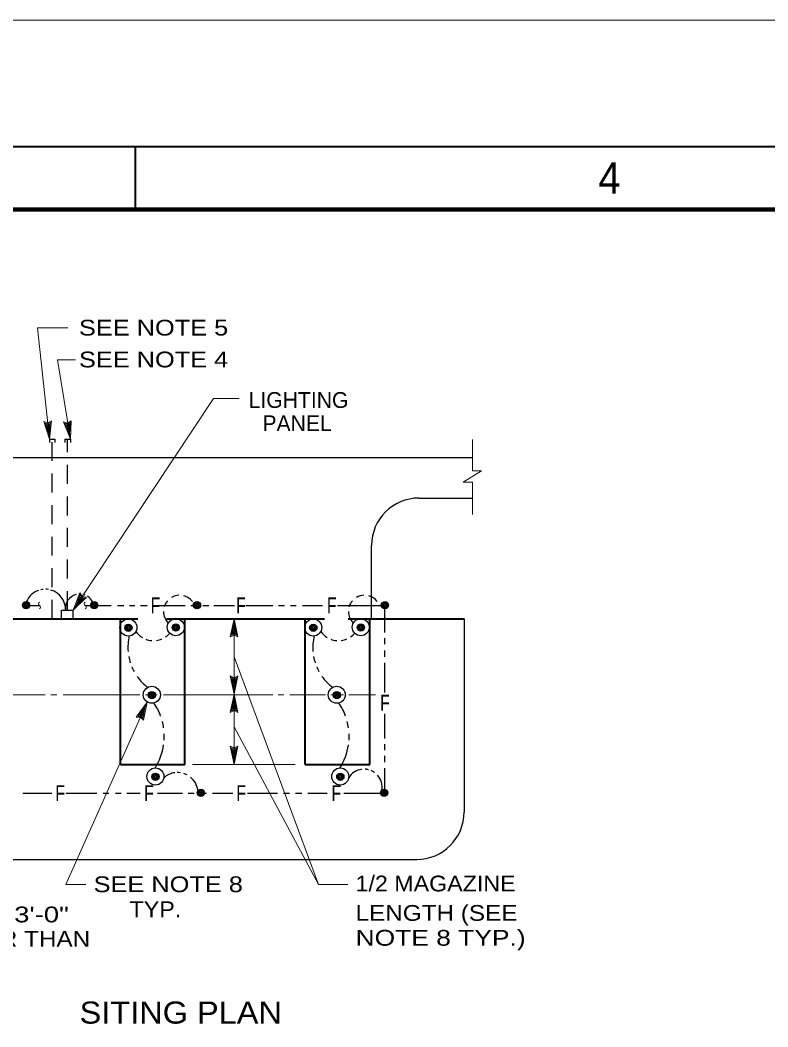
# Model space of a CAD drawing. Extents: x -39.6 to 16.1, y -17.6 to 34.
# Drawn here: x -17.81 to -11.89, y 4.44 to 12.41 of the extents above; entities that cross this region are included whole.
import ezdxf
from ezdxf.enums import TextEntityAlignment as Align

# ---------------------------------------------------------------- set-up
doc = ezdxf.new("R2010")
doc.units = 0
doc.header["$LTSCALE"] = 0.05
doc.linetypes.add('MEDIUM_DASHED', pattern=[4.5, 3, -1.5])
doc.layers.add('1', color=7, linetype='Continuous', lineweight=13)

msp = doc.modelspace()

# ---------------------------------------------------------------- linework, layer by layer
at = {"layer": '1', "lineweight": 40}
for p, q in [((-16.89821, 11.40842), (-16.89821, 10.90842)), ((-18.13621, 7.66742), (-16.87721, 7.66742)), ((-17.01421, 6.51442), (-17.01421, 7.66742)), ((-16.64921, 7.66742), (-15.39721, 7.66742)), ((-16.50321, 6.51442), (-16.50321, 7.66742)), ((-15.55021, 6.51442), (-15.55021, 7.66742)), ((-15.21021, 7.66742), (-14.29321, 7.66742)), ((-15.03921, 6.51442), (-15.03921, 7.66742)), ((-17.01421, 6.51442), (-16.50321, 6.51442)), ((-15.55021, 6.51442), (-15.03921, 6.51442))]:
    msp.add_line(p, q, dxfattribs=at)
at = {"layer": '1'}
for p, q in [((-17.67021, 9.97142), (-17.43121, 9.97142)), ((-17.67021, 9.97142), (-17.57521, 9.08942)), ((-17.51321, 9.71942), (-17.36921, 9.71942)), ((-17.51321, 9.71942), (-17.41021, 9.08942)), ((-16.27821, 9.41242), (-16.07321, 9.41242)), ((-17.57521, 9.08942), (-17.62121, 9.22942)), ((-17.57921, 9.12642), (-17.60921, 9.21742)), ((-17.60921, 9.21742), (-17.58821, 9.21042)), ((-17.58321, 9.16242), (-17.59821, 9.20542)), ((-17.59821, 9.20542), (-17.58721, 9.20242)), ((-17.58821, 9.21042), (-17.56921, 9.22142)), ((-17.58721, 9.20242), (-17.57921, 9.20742)), ((-17.58321, 9.16242), (-17.57921, 9.20742)), ((-17.57921, 9.12642), (-17.56921, 9.22142)), ((-17.57521, 9.08942), (-17.56021, 9.23542)), ((-17.41021, 9.08942), (-17.46421, 9.22642)), ((-17.41621, 9.12642), (-17.45121, 9.21542)), ((-17.45121, 9.21542), (-17.43021, 9.20942)), ((-17.42221, 9.16142), (-17.43921, 9.20442)), ((-17.43921, 9.20442), (-17.42821, 9.20242)), ((-17.43021, 9.20942), (-17.41121, 9.22242)), ((-17.42821, 9.20242), (-17.42021, 9.20742)), ((-17.42221, 9.16142), (-17.42021, 9.20742)), ((-17.41621, 9.12642), (-17.41121, 9.22242)), ((-17.41021, 9.08942), (-17.40321, 9.23642)), ((-14.22521, 8.83842), (-14.22521, 9.08642)), ((-14.29921, 8.74842), (-14.15421, 8.83842)), ((-14.22521, 8.83842), (-14.15421, 8.83842)), ((-14.29921, 8.74842), (-14.22521, 8.74842)), ((-14.22521, 8.49342), (-14.22521, 8.74842)), ((-17.38821, 7.73642), (-17.28321, 7.83942)), ((-17.36821, 7.76742), (-17.33221, 7.85642)), ((-17.36821, 7.76742), (-17.29921, 7.83442)), ((-17.34821, 7.79742), (-17.33121, 7.84042)), ((-17.34821, 7.79742), (-17.31521, 7.82942)), ((-17.33221, 7.85642), (-17.32121, 7.83842)), ((-17.33121, 7.84042), (-17.32521, 7.83142)), ((-17.32521, 7.83142), (-17.31521, 7.82942)), ((-17.32121, 7.83842), (-17.29921, 7.83442)), ((-16.11421, 7.66742), (-16.14521, 7.52342)), ((-16.11421, 7.66742), (-16.08321, 7.52342)), ((-16.11421, 7.63042), (-16.13421, 7.53642)), ((-16.11421, 7.59442), (-16.12321, 7.54942)), ((-16.11421, 7.63042), (-16.09421, 7.53642)), ((-16.11421, 7.59442), (-16.10421, 7.54942)), ((-16.11421, 7.54542), (-16.13421, 7.53642)), ((-16.11421, 7.55342), (-16.12321, 7.54942)), ((-16.10421, 7.54942), (-16.11421, 7.55342)), ((-16.09421, 7.53642), (-16.11421, 7.54542)), ((-16.11421, 7.36542), (-15.44621, 5.56442)), ((-16.11421, 7.07042), (-16.14521, 7.21442)), ((-16.11421, 7.10742), (-16.13421, 7.20142)), ((-16.13421, 7.20142), (-16.11421, 7.19242)), ((-16.11421, 7.14342), (-16.12421, 7.18842)), ((-16.12421, 7.18842), (-16.11421, 7.18442)), ((-16.11421, 7.07042), (-16.08321, 7.21442)), ((-16.11421, 7.10742), (-16.09421, 7.20142)), ((-16.11421, 7.19242), (-16.09421, 7.20142)), ((-16.11421, 7.14342), (-16.10521, 7.18842)), ((-16.11421, 7.18442), (-16.10521, 7.18842)), ((-18.16521, 7.06442), (-17.61021, 7.06442)), ((-17.56621, 7.06442), (-17.51821, 7.06442)), ((-17.46721, 7.06442), (-16.86021, 7.06442)), ((-16.81421, 7.06442), (-16.72321, 7.06442)), ((-16.67421, 7.06442), (-15.80721, 7.06442)), ((-16.11421, 7.07042), (-16.14521, 6.92642)), ((-16.11421, 7.03342), (-16.13421, 6.93942)), ((-16.11421, 7.07042), (-16.08321, 6.92642)), ((-16.11421, 7.03342), (-16.09421, 6.93942)), ((-15.76621, 7.06442), (-15.71921, 7.06442)), ((-15.67321, 7.06442), (-15.38921, 7.06442)), ((-15.34721, 7.06442), (-15.24821, 7.06442)), ((-15.20521, 7.06442), (-14.99521, 7.06442)), ((-16.80221, 7.00842), (-16.88921, 6.88942)), ((-16.81721, 6.97442), (-16.87421, 6.89642)), ((-16.83221, 6.94142), (-16.85821, 6.90442)), ((-16.83221, 6.94142), (-16.84121, 6.89642)), ((-16.81721, 6.97442), (-16.83721, 6.88042)), ((-16.80221, 7.00842), (-16.83221, 6.86442)), ((-16.11421, 6.94842), (-16.13421, 6.93942)), ((-16.11421, 6.99742), (-16.12321, 6.95242)), ((-16.11421, 6.95642), (-16.12321, 6.95242)), ((-16.11421, 6.99742), (-16.10421, 6.95242)), ((-16.10421, 6.95242), (-16.11421, 6.95642)), ((-16.09421, 6.93942), (-16.11421, 6.94842)), ((-16.85221, 6.89742), (-16.87421, 6.89642)), ((-16.84821, 6.90442), (-16.85821, 6.90442)), ((-16.83721, 6.88042), (-16.85221, 6.89742)), ((-16.84121, 6.89642), (-16.84821, 6.90442)), ((-16.11421, 6.51442), (-16.14521, 6.65842)), ((-16.11421, 6.55142), (-16.13421, 6.64542)), ((-16.13421, 6.64542), (-16.11421, 6.63642)), ((-16.11421, 6.58742), (-16.12421, 6.63242)), ((-16.12421, 6.63242), (-16.11421, 6.62842)), ((-16.11421, 6.51442), (-16.08321, 6.65842)), ((-16.11421, 6.55142), (-16.09421, 6.64542)), ((-16.11421, 6.63642), (-16.09421, 6.64542)), ((-16.11421, 6.58742), (-16.10521, 6.63242)), ((-16.11421, 6.62842), (-16.10521, 6.63242)), ((-16.44221, 6.51442), (-15.63021, 6.51442))]:
    msp.add_line(p, q, dxfattribs=at)
at = {"layer": '1', "lineweight": 25}
for p, q in [((-17.57521, 9.08942), (-17.53321, 9.08942)), ((-17.57521, 9.08942), (-17.57521, 9.06342)), ((-17.53321, 9.08942), (-17.53321, 9.06342)), ((-17.45421, 9.08942), (-17.45421, 9.06342)), ((-20.55621, 8.94342), (-14.22521, 8.94342)), ((-14.65021, 8.62342), (-14.22521, 8.62342)), ((-15.02521, 7.66742), (-15.02521, 8.24842)), ((-17.77721, 7.77342), (-17.65521, 7.77342)), ((-17.47921, 7.66742), (-17.47921, 7.73642)), ((-17.47921, 7.73642), (-17.38821, 7.73642)), ((-17.38821, 7.66742), (-17.38821, 7.73642)), ((-17.29221, 7.77342), (-17.08821, 7.77342)), ((-17.03821, 7.77342), (-16.98721, 7.77342)), ((-16.94221, 7.77342), (-16.90021, 7.77342)), ((-16.85521, 7.77342), (-16.80221, 7.77342)), ((-16.71221, 7.77342), (-16.50121, 7.77342)), ((-16.45621, 7.77342), (-16.40921, 7.77342)), ((-16.36021, 7.77342), (-16.31521, 7.77342)), ((-16.27321, 7.77342), (-16.11121, 7.77342)), ((-16.02121, 7.77342), (-15.80821, 7.77342)), ((-15.76321, 7.77342), (-15.71421, 7.77342)), ((-15.66821, 7.77342), (-15.62121, 7.77342)), ((-15.57321, 7.77342), (-15.41321, 7.77342)), ((-15.29521, 7.77342), (-14.92221, 7.77342)), ((-14.92221, 7.77342), (-14.92221, 7.55942)), ((-14.29321, 7.66742), (-14.29321, 6.13642)), ((-14.92221, 7.51442), (-14.92221, 7.46742)), ((-14.92221, 7.41642), (-14.92221, 7.36542)), ((-14.92221, 7.31742), (-14.92221, 7.08242)), ((-14.92221, 6.91442), (-14.92221, 6.71842)), ((-14.92221, 6.67342), (-14.92221, 6.62642)), ((-14.92221, 6.58142), (-14.92221, 6.53242)), ((-14.92221, 6.48542), (-14.92221, 6.28642)), ((-17.78621, 6.28642), (-17.55621, 6.28642)), ((-17.44521, 6.28642), (-17.20121, 6.28642)), ((-17.15021, 6.28642), (-17.10521, 6.28642)), ((-17.05421, 6.28642), (-17.00921, 6.28642)), ((-16.96221, 6.28642), (-16.85821, 6.28642)), ((-16.71921, 6.28642), (-16.52321, 6.28642)), ((-16.47821, 6.28642), (-16.43121, 6.28642)), ((-16.38021, 6.28642), (-16.33121, 6.28642)), ((-16.28621, 6.28642), (-16.12521, 6.28642)), ((-16.00721, 6.28642), (-15.77021, 6.28642)), ((-15.72321, 6.28642), (-15.67421, 6.28642)), ((-15.62721, 6.28642), (-15.57821, 6.28642)), ((-15.53121, 6.28642), (-15.37821, 6.28642)), ((-15.24621, 6.28642), (-14.92221, 6.28642)), ((-20.29221, 5.76142), (-14.66821, 5.76142))]:
    msp.add_line(p, q, dxfattribs=at)
at = {"layer": '1', "linetype": 'MEDIUM_DASHED', "lineweight": 25}
for p, q in [((-17.55521, 7.66742), (-17.55521, 9.08942)), ((-17.43421, 7.73642), (-17.43421, 9.08942))]:
    msp.add_line(p, q, dxfattribs=at)
at = {"layer": '1'}
for points in [[(-25.89821, 12.40842), (16.10179, 12.40842), (16.10179, -17.59158)], [(-16.27821, 9.41242), (-17.38821, 7.73642), (-17.33421, 7.87342)], [(-17.62121, 9.22942), (-17.58921, 9.21842), (-17.56021, 9.23542)], [(-17.46421, 9.22642), (-17.43121, 9.21742), (-17.40321, 9.23642)], [(-17.33421, 7.87342), (-17.31621, 7.84442), (-17.28321, 7.83942)], [(-16.11421, 6.51442), (-16.11421, 7.07042), (-16.11421, 7.66742)], [(-16.08321, 7.52342), (-16.11421, 7.53742), (-16.14521, 7.52342)], [(-16.14521, 7.21442), (-16.11421, 7.20042), (-16.08321, 7.21442)], [(-16.80221, 7.00842), (-17.44521, 5.56442), (-17.28721, 5.56442)], [(-16.08321, 6.92642), (-16.11421, 6.94042), (-16.14521, 6.92642)], [(-16.83221, 6.86442), (-16.85521, 6.88942), (-16.88921, 6.88942)], [(-16.11421, 6.81242), (-15.44621, 5.56442), (-15.21421, 5.56442)], [(-16.14521, 6.65842), (-16.11421, 6.64442), (-16.08321, 6.65842)]]:
    msp.add_lwpolyline(points, dxfattribs=at)
at = {"layer": '1', "lineweight": 40}
msp.add_lwpolyline([(-24.89821, -16.59158), (-24.89821, 11.40842), (15.10179, 11.40842), (15.10179, -16.59158)], close=True, dxfattribs=at)
at = {"layer": '1', "lineweight": 90}
msp.add_lwpolyline([(-23.39821, 10.90842), (14.60179, 10.90842), (14.60179, -16.09158), (-23.39821, -16.09158)], close=True, dxfattribs=at)
at = {"layer": '1', "lineweight": 25}
msp.add_lwpolyline([(-17.45421, 9.08942), (-17.41021, 9.08942), (-17.41021, 9.06342)], dxfattribs=at)
for centre, radius in [((-17.76083, 7.77548), 0.02891), ((-17.76083, 7.77548), 0.02242), ((-17.76083, 7.77548), 0.01644), ((-17.76083, 7.77548), 0.0083), ((-17.22183, 7.77548), 0.02891), ((-17.22183, 7.77548), 0.02242), ((-17.22183, 7.77548), 0.01644), ((-17.22183, 7.77548), 0.0083), ((-16.40783, 7.77548), 0.02891), ((-16.40783, 7.77548), 0.02242), ((-16.40783, 7.77548), 0.01644), ((-16.40783, 7.77548), 0.0083), ((-14.91983, 7.77548), 0.02891), ((-14.91983, 7.77548), 0.02242), ((-14.91983, 7.77548), 0.01644), ((-14.91983, 7.77548), 0.0083), ((-16.95121, 7.59842), 0.06748), ((-16.57521, 7.60042), 0.06748), ((-15.48721, 7.59842), 0.06748), ((-15.11121, 7.60042), 0.06748), ((-16.95083, 7.59648), 0.02891), ((-16.95083, 7.59648), 0.02242), ((-16.95083, 7.59648), 0.01644), ((-16.95083, 7.59648), 0.0083), ((-16.57483, 7.59848), 0.02891), ((-16.57483, 7.59848), 0.02242), ((-16.57483, 7.59848), 0.01644), ((-16.57483, 7.59848), 0.0083), ((-15.48683, 7.59648), 0.02891), ((-15.48683, 7.59648), 0.02242), ((-15.48683, 7.59648), 0.01644), ((-15.48683, 7.59648), 0.0083), ((-15.11083, 7.59848), 0.02891), ((-15.11083, 7.59848), 0.02242), ((-15.11083, 7.59848), 0.01644), ((-15.11083, 7.59848), 0.0083), ((-16.76521, 7.06542), 0.06748), ((-15.30121, 7.06542), 0.06748), ((-16.76483, 7.06348), 0.02891), ((-16.76483, 7.06348), 0.02242), ((-16.76483, 7.06348), 0.01644), ((-16.76483, 7.06348), 0.0083), ((-15.30083, 7.06348), 0.02891), ((-15.30083, 7.06348), 0.02242), ((-15.30083, 7.06348), 0.01644), ((-15.30083, 7.06348), 0.0083), ((-16.73721, 6.41842), 0.06748), ((-15.27321, 6.41842), 0.06748), ((-16.73683, 6.41648), 0.02891), ((-16.73683, 6.41648), 0.02242), ((-16.73683, 6.41648), 0.01644), ((-16.73683, 6.41648), 0.0083), ((-15.27283, 6.41648), 0.02891), ((-15.27283, 6.41648), 0.02242), ((-15.27283, 6.41648), 0.01644), ((-15.27283, 6.41648), 0.0083), ((-16.37783, 6.28848), 0.02891), ((-16.37783, 6.28848), 0.02242), ((-16.37783, 6.28848), 0.01644), ((-14.92683, 6.28848), 0.02891), ((-14.92683, 6.28848), 0.02242), ((-14.92683, 6.28848), 0.01644), ((-16.37783, 6.28848), 0.0083), ((-14.92683, 6.28848), 0.0083)]:
    msp.add_circle(centre, radius, dxfattribs=at)
for centre, radius, start, end in [((-14.65021, 8.24842), 0.375, 90, 180), ((-17.6097, 7.7399), 0.16153, 95.51978, 102.08511), ((-17.6097, 7.7399), 0.16153, 80.92201, 88.39851), ((-17.6097, 7.7399), 0.16153, 358.76497, 73.45795), ((-17.6097, 7.7399), 0.16153, 109.11489, 156.84363), ((-17.33587, 7.74959), 0.1141, 105.05257, 186.63192), ((-17.33587, 7.74959), 0.1141, 84.15174, 94.19147), ((-17.33587, 7.74959), 0.1141, 67.58065, 75.01745), ((-17.33587, 7.74959), 0.1141, 27.0109, 57.77622), ((-16.54521, 7.72558), 0.12812, 92.31217, 119.67381), ((-16.54521, 7.72558), 0.12812, 37.97304, 74.64705), ((-15.08121, 7.72558), 0.12812, 92.31217, 119.67381), ((-15.08121, 7.72558), 0.12812, 37.97304, 74.64705), ((-16.54521, 7.72558), 0.12812, 138.45731, 163.45632), ((-15.08121, 7.72558), 0.12812, 138.45731, 163.45632), ((-16.54521, 7.72558), 0.12812, 180.07346, 226.00139), ((-15.08121, 7.72558), 0.12812, 180.07346, 226.00139), ((-16.56002, 7.43955), 0.39502, 166.55144, 184.64806), ((-16.75212, 7.66682), 0.17235, 215.62869, 239.35965), ((-16.75212, 7.66682), 0.17235, 249.22563, 265.63288), ((-16.75212, 7.66682), 0.17235, 277.50113, 292.89982), ((-16.75212, 7.66682), 0.17235, 303.86286, 318.41281), ((-15.09602, 7.43955), 0.39502, 166.55144, 184.64806), ((-15.28812, 7.66682), 0.17235, 215.62869, 239.35965), ((-15.28812, 7.66682), 0.17235, 249.22563, 265.63288), ((-15.28812, 7.66682), 0.17235, 277.50113, 292.89982), ((-15.28812, 7.66682), 0.17235, 303.86286, 318.41281), ((-16.56002, 7.43955), 0.39502, 190.46253, 197.79365), ((-15.09602, 7.43955), 0.39502, 190.46253, 197.79365), ((-16.56002, 7.43955), 0.39502, 202.86164, 208.84607), ((-15.09602, 7.43955), 0.39502, 202.86164, 208.84607), ((-16.56002, 7.43955), 0.39502, 215.36971, 232.91665), ((-15.09602, 7.43955), 0.39502, 215.36971, 232.91665), ((-17.13574, 6.73683), 0.46868, 20.02769, 34.22173), ((-15.67174, 6.73683), 0.46868, 20.02769, 34.22173), ((-17.13574, 6.73683), 0.46868, 8.31283, 14.59112), ((-15.67174, 6.73683), 0.46868, 8.31283, 14.59112), ((-17.13574, 6.73683), 0.46868, 356.16372, 2.37301), ((-15.67174, 6.73683), 0.46868, 356.16372, 2.37301), ((-17.13574, 6.73683), 0.46868, 327.5582, 351.70708), ((-15.67174, 6.73683), 0.46868, 327.5582, 351.70708), ((-15.08468, 6.33434), 0.14233, 97.82788, 148.63789), ((-15.08468, 6.33434), 0.14233, 75.40704, 86.68224), ((-15.08468, 6.33434), 0.14233, 53.70001, 66.74486), ((-16.5612, 6.28987), 0.16031, 97.75777, 132.84098), ((-16.5612, 6.28987), 0.16031, 81.39526, 91.08697), ((-16.5612, 6.28987), 0.16031, 62.06661, 72.31889), ((-16.5612, 6.28987), 0.16031, 7.36455, 50.14001), ((-15.08468, 6.33434), 0.14233, 350.73009, 41.47656), ((-14.66821, 6.13642), 0.375, 270, 0)]:
    msp.add_arc(centre, radius, start, end, dxfattribs=at)
at = {"layer": '1'}
for centre, start, end in [((-17.6489, 7.78642), 115.90014, 244.09986), ((-17.66152, 7.76042), 295.90014, 64.09986), ((-17.2859, 7.78642), 115.90014, 244.09986), ((-17.29852, 7.76042), 295.90014, 64.09986)]:
    msp.add_arc(centre, 0.01445, start, end, dxfattribs=at)

# ---------------------------------------------------------------- texts
for s, height, width, p in [('4', 0.25, 0.95, (-13.14171, 11.03342)), ('F', 0.125, 0.75, (-16.73671, 7.71142)), ('F', 0.125, 0.75, (-16.05971, 7.71142)), ('F', 0.125, 0.75, (-15.34071, 7.71142)), ('F', 0.125, 0.75, (-14.91971, 6.94042)), ('F', 0.125, 0.75, (-17.49071, 6.22442)), ('F', 0.125, 0.75, (-16.78771, 6.22442)), ('F', 0.125, 0.75, (-16.05771, 6.22442)), ('F', 0.125, 0.75, (-15.30471, 6.22442)), ('SITING PLAN', 0.175, 1.1, (-16.53621, 4.46142))]:
    msp.add_text(s, height=height, dxfattribs=dict(at, width=width)).set_placement(p, align=Align.CENTER)
for s, width, p in [('SEE NOTE 5', 1.2, (-17.34221, 9.91042)), ('SEE NOTE 4', 1.2, (-17.34221, 9.65842)), ('SEE NOTE 8', 1.2, (-17.22621, 5.50242)), ('1/2 MAGAZINE', 1.1, (-15.15221, 5.50842)), ('TYP.', 1.1, (-16.94121, 5.30442)), ('NOT LESS THAN 3\'-0"', 1.3, (-19.64221, 5.26342)), ('LENGTH (SEE', 1.15, (-15.15221, 5.27542)), ('(91) NOR GREATER THAN', 1.15, (-19.63521, 5.07042)), ('NOTE 8 TYP.)', 1.25, (-15.15221, 5.07842))]:
    msp.add_text(s, height=0.125, dxfattribs=dict(at, width=width)).set_placement(p)
for s, p in [('LIGHTING', (-15.99821, 9.33742)), ('PANEL', (-15.88921, 9.15342))]:
    msp.add_text(s, height=0.125, dxfattribs=at).set_placement(p)

doc.saveas('drawing.dxf')
